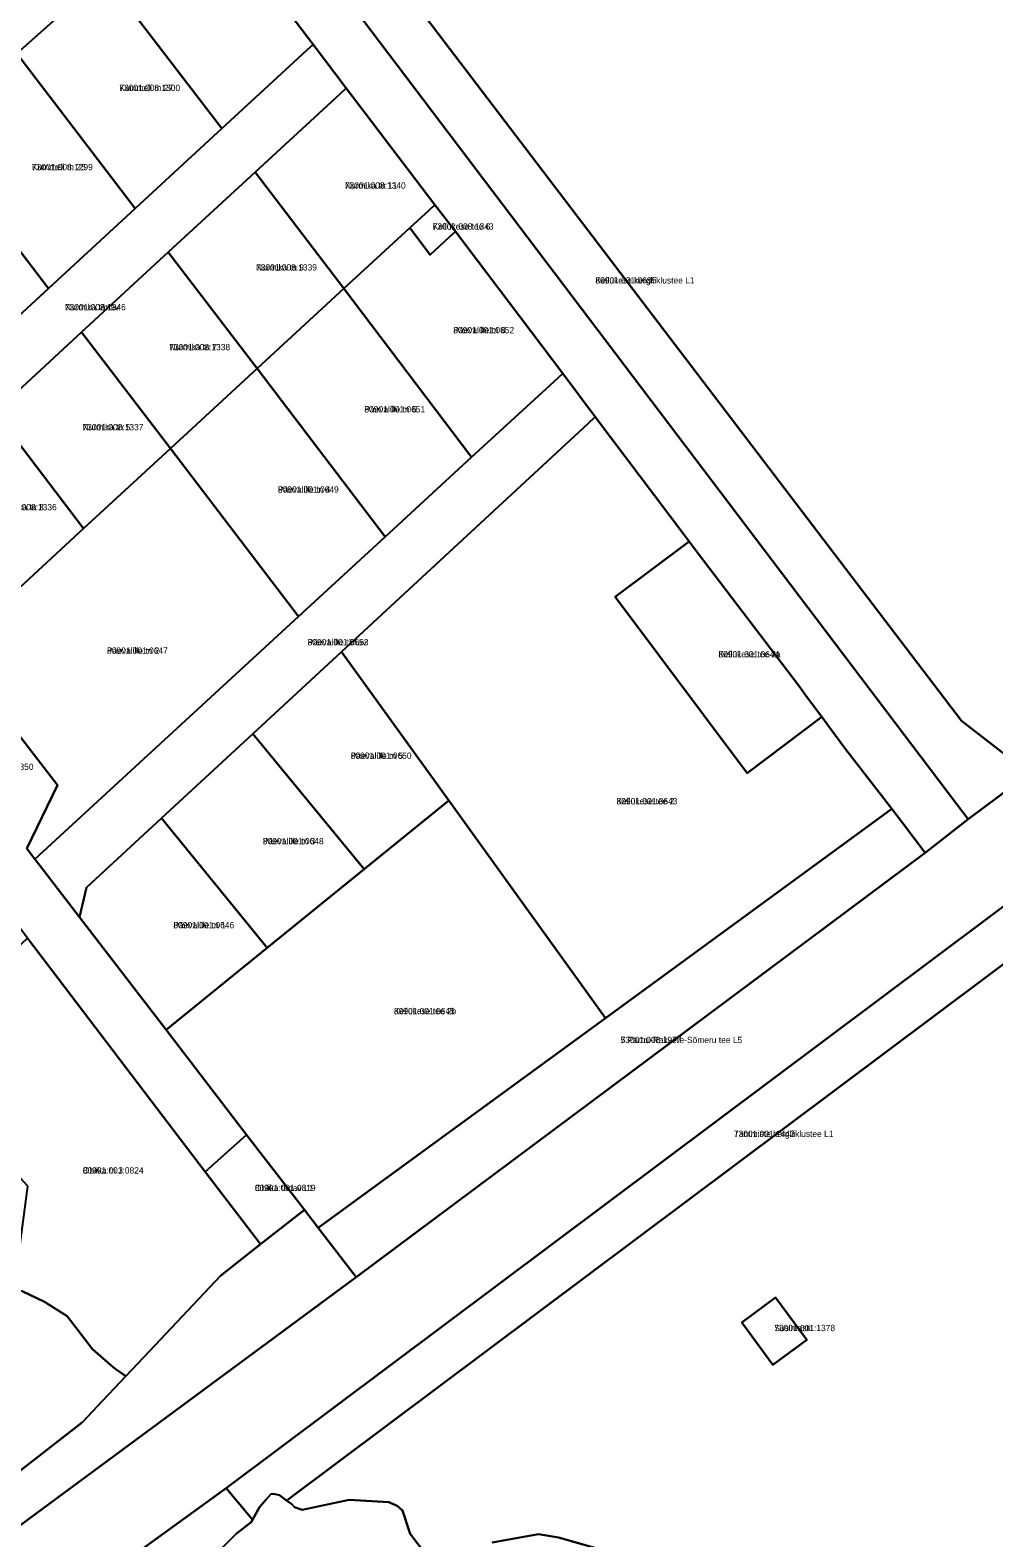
# Model space of a CAD drawing. Extents: x 524000 to 564260, y 6469338 to 6496391.
# Drawn here: x 535400.5 to 535630.3, y 6472024.8 to 6472384.2 of the extents above; entities that cross this region are included whole.
import ezdxf

# ---------------------------------------------------------------- set-up
doc = ezdxf.new("R2010")
doc.units = 0
for name, color, linetype in [('L_AADRESS', 7, 'Continuous'), ('PIIR', 7, 'Continuous'), ('TUNNUS', 7, 'Continuous')]:
    doc.layers.add(name, color=color, linetype=linetype)

msp = doc.modelspace()

# ---------------------------------------------------------------- linework, layer by layer
at = {"layer": 'PIIR'}
for points in [[(535638.82, 6472207.03), (535622.55, 6472219.54), (535441.36, 6472457.53), (535548.96, 6472541.19), (535549.64, 6472541.69), (535575.33, 6472561.44), (535627.92, 6472601.87), (535638.27, 6472609.83)], [(535431.76, 6472450.18), (535621.36, 6472199.81), (535624.16, 6472196.1), (535613.88, 6472188.1), (535608.49, 6472195.22), (535605.96, 6472198.55), (535594.97, 6472212.76), (535593.65, 6472214.55), (535591.19, 6472217.88), (535589.24, 6472220.5), (535586.1, 6472224.75), (535585.22, 6472225.94), (535583.83, 6472227.82), (535559.83, 6472259.42), (535557.63, 6472262.34), (535556.45, 6472263.9), (535553.07, 6472268.39), (535535.27, 6472292.01), (535527.49, 6472302.34), (535501.95, 6472336.23), (535496.98, 6472342.53), (535475.91, 6472370.37), (535468.03, 6472380.78), (535440.44, 6472417.07)], [(535418.29, 6472397.33), (535397.32, 6472378.65), (535376.36, 6472359.97), (535355.39, 6472341.29), (535334.42, 6472322.61), (535313.08, 6472303.59), (535299.14, 6472300.3), (535287.77, 6472295.76), (535266.99, 6472284.97), (535264.96, 6472283.92), (535243.16, 6472267.54), (535239.34, 6472264.68), (535220.83, 6472248.19), (535198.74, 6472228.5), (535176.65, 6472208.82), (535154.56, 6472189.13), (535132.47, 6472169.45), (535110.37, 6472149.76)], [(535681.04, 6472211.61), (535447.26, 6472036.65), (535417.01, 6472014.71)], [(535298.79, 6471954.5), (535478.29, 6472086.95), (535613.88, 6472188.1), (535624.16, 6472196.1), (535638.82, 6472207.03)], [(535496.05, 6472019.34), (535491.1, 6472025.79), (535489.27, 6472031.34), (535488.04, 6472032.44), (535486.01, 6472033.33), (535476.57, 6472033.9), (535465.35, 6472031.47), (535463.57, 6472032.11), (535462.91, 6472032.82), (535461.67, 6472033.75), (535461.79, 6472033.84), (535687.89, 6472202.97)], [(535398.63, 6472083.62), (535403.92, 6472081.11), (535409.37, 6472077.69), (535415.41, 6472069.78), (535419.77, 6472066.01), (535420.71, 6472065.2), (535423.36, 6472063.39), (535417.85, 6472057.58), (535412.98, 6472052.43), (535381.36, 6472027.86)], [(535447.83, 6472023.99), (535449.61, 6472025.76), (535453.25, 6472028.55), (535453.57, 6472029.14), (535455.21, 6472032.18), (535456.72, 6472033.88), (535457.95, 6472035.27), (535458.57, 6472035.32), (535459.97, 6472035.04), (535461.67, 6472033.75), (535462.91, 6472032.82), (535463.57, 6472032.11), (535465.35, 6472031.47), (535476.57, 6472033.9), (535486.01, 6472033.33), (535488.04, 6472032.44), (535489.27, 6472031.34), (535491.1, 6472025.79), (535496.05, 6472019.34)], [(535544.64, 6472019.76), (535526.52, 6472024.88), (535521.75, 6472025.67), (535510.64, 6472023.76)], [(535510.64, 6472023.76), (535521.75, 6472025.67), (535526.52, 6472024.88), (535544.64, 6472019.76)]]:
    msp.add_lwpolyline(points, dxfattribs=at)
for points in [[(535621.36, 6472199.81), (535431.76, 6472450.18), (535441.36, 6472457.53), (535622.55, 6472219.54), (535638.82, 6472207.03), (535624.16, 6472196.1)], [(535418.29, 6472397.33), (535438.9, 6472415.7), (535440.44, 6472417.07), (535468.03, 6472380.78), (535466.53, 6472379.4), (535446.24, 6472360.71)], [(535397.32, 6472378.65), (535418.29, 6472397.33), (535446.24, 6472360.71), (535425.56, 6472341.66)], [(535341.6, 6472264.32), (535363.5, 6472284.49), (535384.18, 6472303.54), (535404.88, 6472322.61), (535425.56, 6472341.66), (535446.24, 6472360.71), (535466.53, 6472379.4), (535468.03, 6472380.78), (535475.91, 6472370.37), (535474.45, 6472369.02), (535454.15, 6472350.33), (535433.47, 6472331.28), (535412.79, 6472312.23), (535392.1, 6472293.17), (535371.42, 6472274.12), (535349.61, 6472254.03)], [(535376.36, 6472359.97), (535397.32, 6472378.65), (535425.56, 6472341.66), (535404.88, 6472322.61)], [(535454.15, 6472350.33), (535474.45, 6472369.02), (535475.91, 6472370.37), (535496.98, 6472342.53), (535495.57, 6472341.23), (535491.06, 6472337.07), (535475.33, 6472322.58)], [(535355.39, 6472341.29), (535376.36, 6472359.97), (535404.88, 6472322.61), (535384.18, 6472303.54)], [(535433.47, 6472331.28), (535454.15, 6472350.33), (535475.33, 6472322.58), (535454.62, 6472303.51)], [(535491.06, 6472337.07), (535495.57, 6472341.23), (535496.98, 6472342.53), (535501.95, 6472336.23), (535500.42, 6472334.83), (535495.92, 6472330.67)], [(535501.95, 6472336.23), (535527.49, 6472302.34), (535525.43, 6472300.44), (535505.79, 6472282.37), (535475.33, 6472322.58), (535491.06, 6472337.07), (535495.92, 6472330.67), (535500.42, 6472334.83)], [(535412.79, 6472312.23), (535433.47, 6472331.28), (535454.62, 6472303.51), (535433.97, 6472284.48)], [(535475.33, 6472322.58), (535505.79, 6472282.37), (535485.2, 6472263.45), (535454.62, 6472303.51)], [(535392.1, 6472293.17), (535412.79, 6472312.23), (535433.97, 6472284.48), (535413.29, 6472265.39)], [(535362.97, 6472216.3), (535340.78, 6472245.55), (535325.27, 6472265.94), (535299.14, 6472300.3), (535313.08, 6472303.59), (535315.57, 6472298.54), (535341.6, 6472264.32), (535349.61, 6472254.03), (535370.94, 6472226.42), (535382.02, 6472236.62), (535407.04, 6472204.23), (535399.76, 6472189.17), (535401.66, 6472186.63), (535402.87, 6472185.09), (535412.32, 6472172.76), (535432.95, 6472145.9), (535452.15, 6472120.89), (535442.26, 6472112.1), (535399.94, 6472167.74), (535392.62, 6472177.34)], [(535525.43, 6472300.44), (535527.49, 6472302.34), (535535.27, 6472292.01), (535533.5, 6472290.38), (535474.73, 6472236.05), (535453.59, 6472216.49), (535431.87, 6472196.4), (535413.96, 6472179.84), (535412.32, 6472172.76), (535402.87, 6472185.09), (535401.66, 6472186.63), (535464.51, 6472244.43), (535485.2, 6472263.45), (535505.79, 6472282.37)], [(535454.62, 6472303.51), (535485.2, 6472263.45), (535464.51, 6472244.43), (535433.97, 6472284.48)], [(535371.42, 6472274.12), (535392.1, 6472293.17), (535413.29, 6472265.39), (535392.58, 6472246.36)], [(535533.5, 6472290.38), (535535.27, 6472292.01), (535553.07, 6472268.39), (535556.45, 6472263.9), (535557.63, 6472262.34), (535539.99, 6472249.14), (535571.49, 6472207.08), (535589.24, 6472220.5), (535591.19, 6472217.88), (535593.65, 6472214.55), (535594.97, 6472212.76), (535605.96, 6472198.55), (535537.66, 6472148.7), (535500.33, 6472200.55), (535474.73, 6472236.05)], [(535433.97, 6472284.48), (535464.51, 6472244.43), (535401.66, 6472186.63), (535399.76, 6472189.17), (535407.04, 6472204.23), (535382.02, 6472236.62), (535392.58, 6472246.36), (535413.29, 6472265.39)], [(535539.99, 6472249.14), (535557.63, 6472262.34), (535559.83, 6472259.42), (535583.83, 6472227.82), (535585.22, 6472225.94), (535586.1, 6472224.75), (535589.24, 6472220.5), (535571.49, 6472207.08)], [(535480.14, 6472184.19), (535453.59, 6472216.49), (535474.73, 6472236.05), (535500.33, 6472200.55)], [(535457.04, 6472165.45), (535431.87, 6472196.4), (535453.59, 6472216.49), (535480.14, 6472184.19)], [(535453.57, 6472029.14), (535452.56, 6472030.34), (535447.26, 6472036.65), (535681.04, 6472211.61), (535687.89, 6472202.97), (535461.79, 6472033.84), (535461.67, 6472033.75), (535459.97, 6472035.04), (535458.57, 6472035.32), (535457.95, 6472035.27), (535456.72, 6472033.88), (535455.21, 6472032.18)], [(535480.14, 6472184.19), (535500.33, 6472200.55), (535537.66, 6472148.7), (535469.22, 6472098.73), (535465.93, 6472103.05), (535452.15, 6472120.89), (535432.95, 6472145.9), (535457.04, 6472165.45)], [(535432.95, 6472145.9), (535412.32, 6472172.76), (535413.96, 6472179.84), (535431.87, 6472196.4), (535457.04, 6472165.45)], [(535469.22, 6472098.73), (535537.66, 6472148.7), (535605.96, 6472198.55), (535608.49, 6472195.22), (535613.88, 6472188.1), (535478.29, 6472086.95)], [(535400, 6472108.63), (535370.68, 6472140.51), (535399.94, 6472167.74), (535442.26, 6472112.1), (535455.45, 6472094.81), (535445.91, 6472087.3), (535428.99, 6472069.36), (535423.36, 6472063.39), (535420.71, 6472065.2), (535419.77, 6472066.01), (535415.41, 6472069.78), (535409.37, 6472077.69), (535403.92, 6472081.11), (535398.63, 6472083.62), (535396.67, 6472083.7), (535397.75, 6472091.8)], [(535455.45, 6472094.81), (535442.26, 6472112.1), (535452.15, 6472120.89), (535465.93, 6472103.05)], [(535264.68, 6471941.76), (535285.62, 6471957.21), (535302.63, 6471969.76), (535381.36, 6472027.86), (535412.98, 6472052.43), (535417.85, 6472057.58), (535423.36, 6472063.39), (535428.99, 6472069.36), (535445.91, 6472087.3), (535455.45, 6472094.81), (535465.93, 6472103.05), (535469.22, 6472098.73), (535478.29, 6472086.95), (535298.79, 6471954.5), (535270.76, 6471933.77)], [(535577.61, 6472066.1), (535570.2, 6472076.16), (535578.25, 6472082.09), (535585.66, 6472072.03)], [(535570.2, 6472076.16), (535577.61, 6472066.1), (535585.66, 6472072.03), (535578.25, 6472082.09)], [(535406.46, 6472006.89), (535417.01, 6472014.71), (535447.26, 6472036.65), (535452.56, 6472030.34), (535453.57, 6472029.14), (535453.25, 6472028.55), (535449.61, 6472025.76), (535447.83, 6472023.99), (535443.69, 6472019.87), (535440.76, 6472014.03), (535443.82, 6472007.92), (535449.93, 6472006.13), (535460.88, 6472005.88), (535464.3, 6472006.98), (535467.45, 6472008), (535467.5, 6472007.96), (535473.28, 6472005.97), (535475.51, 6472002.85), (535473.53, 6472000.07), (535459.83, 6471980.9), (535451.41, 6471976.33), (535433.57, 6471968.73)]]:
    msp.add_lwpolyline(points, close=True, dxfattribs=at)

# ---------------------------------------------------------------- texts
at = {"layer": 'L_AADRESS'}
for s, p in [('Kummeli tn 27', (535421.78, 6472369.68)), ('Kummeli tn 25', (535400.96, 6472350.81)), ('Nurmika tn 11', (535475.56, 6472346.42)), ('Kellukese tee 6', (535496.51, 6472336.65)), ('Nurmika tn 9', (535454.4, 6472326.9)), ('Kellukese kergliiklustee L1', (535535.29, 6472323.81)), ('Nurmika tänav', (535408.82, 6472317.41)), ('Päevalille tn 8', (535501.41, 6472311.94)), ('Nurmika tn 7', (535433.7, 6472307.9)), ('Päevalille tn 6', (535480.2, 6472293.07)), ('Nurmika tn 5', (535413.04, 6472288.82)), ('Päevalille tn 4', (535459.59, 6472273.95)), ('Nurmika tn 3', (535392.36, 6472269.75)), ('Päevalille tn 2', (535418.85, 6472235.55)), ('Päevalille tänav', (535466.69, 6472237.55)), ('Kellukese tee 2a', (535564.62, 6472234.69)), ('Päevalille tn 5', (535476.96, 6472210.51)), ('Kellukese tee 2', (535540.34, 6472199.66)), ('Päevalille tn 3', (535456, 6472190.14)), ('Päevalille tn 1', (535434.68, 6472170.12)), ('Kellukese tee 2b', (535487.27, 6472149.64)), ('5 Pärnu-Rakvere-Sõmeru tee L5', (535541.3, 6472142.75)), ('Tammiste kergliiklustee L1', (535568.3, 6472120.38)), ('Oblika tn 3', (535413.07, 6472111.67)), ('Oblika tänav L1', (535454.09, 6472107.48)), ('Susimasti', (535577.93, 6472074.1))]:
    msp.add_text(s, height=1.5, dxfattribs=at).set_placement(p)
at = {"layer": 'TUNNUS'}
for s, p in [('73001:008:1300', (535421.78, 6472369.68)), ('73001:008:1299', (535400.96, 6472350.81)), ('73001:008:1340', (535475.56, 6472346.42)), ('73001:008:1343', (535496.51, 6472336.65)), ('73001:008:1339', (535454.4, 6472326.9)), ('80901:001:0685', (535535.29, 6472323.81)), ('73001:008:1346', (535408.82, 6472317.41)), ('80901:001:0652', (535501.41, 6472311.94)), ('73001:008:1338', (535433.7, 6472307.9)), ('80901:001:0651', (535480.2, 6472293.07)), ('73001:008:1337', (535413.04, 6472288.82)), ('80901:001:0649', (535459.59, 6472273.95)), ('73001:008:1336', (535392.36, 6472269.75)), ('80901:001:0647', (535418.85, 6472235.55)), ('80901:001:0653', (535466.69, 6472237.55)), ('80901:001:0644', (535564.62, 6472234.69)), ('80901:001:0650', (535476.96, 6472210.51)), ('73001:008:1350', (535386.83, 6472207.85)), ('80901:001:0643', (535540.34, 6472199.66)), ('80901:001:0648', (535456, 6472190.14)), ('80901:001:0646', (535434.68, 6472170.12)), ('80901:001:0645', (535487.27, 6472149.64)), ('73001:008:1977', (535541.3, 6472142.75)), ('73001:001:1442', (535568.3, 6472120.38)), ('80901:001:0824', (535413.07, 6472111.67)), ('80901:001:0819', (535454.09, 6472107.48)), ('73001:001:1378', (535577.93, 6472074.1))]:
    msp.add_text(s, height=1.5, dxfattribs=at).set_placement(p)

doc.saveas('drawing.dxf')
